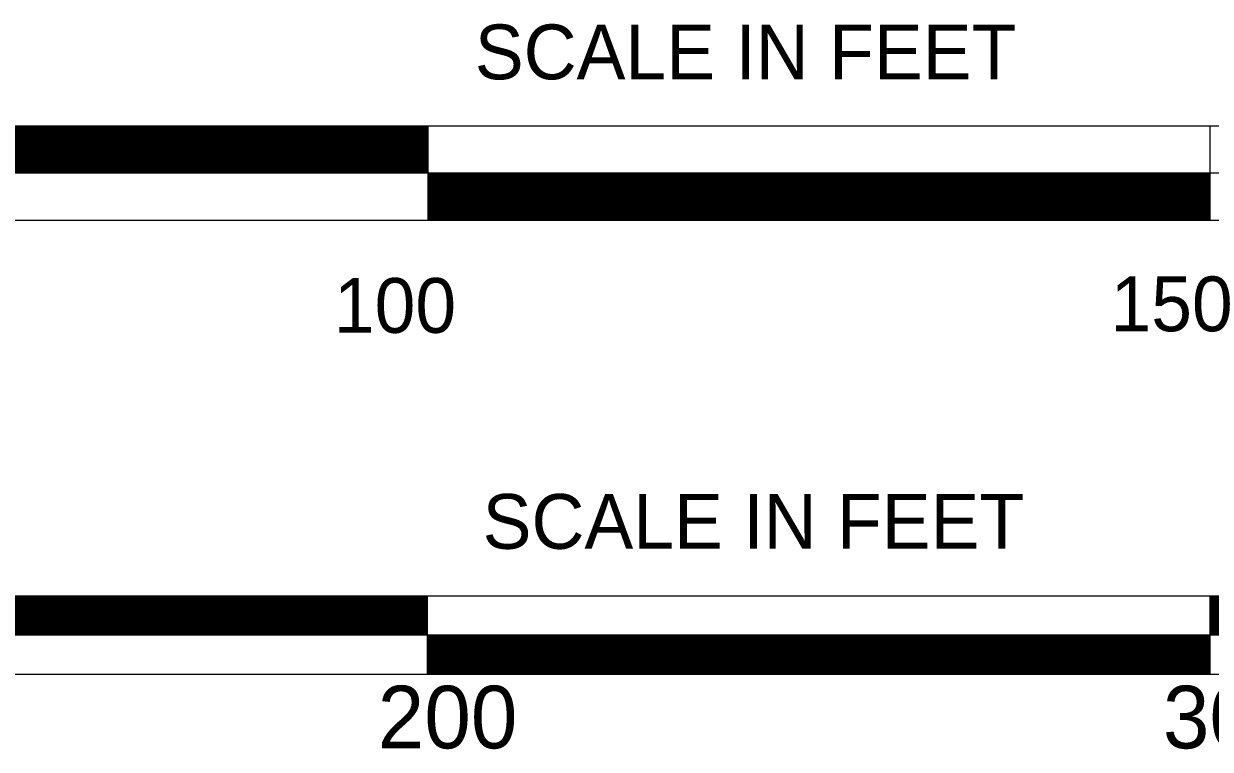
# Model space of a CAD drawing. Extents: x 2147716 to 2176321, y 2125040 to 2131750.
# Drawn here: x 2170114.1 to 2170265.7, y 2129144.4 to 2129237.1 of the extents above; entities that cross this region are included whole.
import ezdxf

# ---------------------------------------------------------------- set-up
doc = ezdxf.new("R2010")
doc.units = 0
doc.layers.add('MAP DATA', color=7, linetype='Continuous')

msp = doc.modelspace()

# ---------------------------------------------------------------- linework, layer by layer
at = {"layer": 'MAP DATA'}
for p, q in [((2170465.63, 2129223.98), (2169965.63, 2129223.98)), ((2170165.73, 2129223.98), (2170065.63, 2129223.98)), ((2170165.73, 2129223.88), (2170065.63, 2129223.88)), ((2170165.73, 2129223.78), (2170065.63, 2129223.78)), ((2170165.73, 2129223.68), (2170065.63, 2129223.68)), ((2170165.73, 2129223.58), (2170065.63, 2129223.58)), ((2170165.73, 2129223.48), (2170065.63, 2129223.48)), ((2170165.73, 2129223.38), (2170065.63, 2129223.38)), ((2170165.73, 2129223.28), (2170065.63, 2129223.28)), ((2170165.73, 2129223.18), (2170065.63, 2129223.18)), ((2170165.73, 2129223.08), (2170065.63, 2129223.08)), ((2170165.73, 2129222.98), (2170065.63, 2129222.98)), ((2170165.73, 2129222.88), (2170065.63, 2129222.88)), ((2170165.73, 2129222.78), (2170065.63, 2129222.78)), ((2170165.73, 2129222.68), (2170065.63, 2129222.68)), ((2170165.73, 2129222.58), (2170065.63, 2129222.58)), ((2170165.73, 2129223.98), (2170165.73, 2129211.98)), ((2170265.63, 2129223.98), (2170265.63, 2129211.98)), ((2170165.73, 2129222.48), (2170065.63, 2129222.48)), ((2170165.73, 2129222.38), (2170065.63, 2129222.38)), ((2170165.73, 2129222.28), (2170065.63, 2129222.28)), ((2170165.73, 2129222.18), (2170065.63, 2129222.18)), ((2170165.73, 2129222.08), (2170065.63, 2129222.08)), ((2170165.73, 2129221.98), (2170065.63, 2129221.98)), ((2170165.73, 2129221.88), (2170065.63, 2129221.88)), ((2170165.73, 2129221.78), (2170065.63, 2129221.78)), ((2170165.73, 2129221.68), (2170065.63, 2129221.68)), ((2170165.73, 2129221.58), (2170065.63, 2129221.58)), ((2170165.73, 2129221.48), (2170065.63, 2129221.48)), ((2170165.73, 2129221.38), (2170065.63, 2129221.38)), ((2170165.73, 2129221.28), (2170065.63, 2129221.28)), ((2170165.73, 2129221.18), (2170065.63, 2129221.18)), ((2170165.73, 2129221.08), (2170065.63, 2129221.08)), ((2170165.73, 2129220.98), (2170065.63, 2129220.98)), ((2170165.73, 2129220.88), (2170065.63, 2129220.88)), ((2170165.73, 2129220.78), (2170065.63, 2129220.78)), ((2170165.73, 2129220.68), (2170065.63, 2129220.68)), ((2170165.73, 2129220.58), (2170065.63, 2129220.58)), ((2170165.73, 2129220.48), (2170065.63, 2129220.48)), ((2170165.73, 2129220.38), (2170065.63, 2129220.38)), ((2170165.73, 2129220.28), (2170065.63, 2129220.28)), ((2170165.73, 2129220.18), (2170065.63, 2129220.18)), ((2170165.73, 2129220.08), (2170065.63, 2129220.08)), ((2170165.73, 2129219.98), (2170065.63, 2129219.98)), ((2170165.73, 2129219.88), (2170065.63, 2129219.88)), ((2170165.73, 2129219.88), (2170065.63, 2129219.88)), ((2170165.73, 2129219.78), (2170065.63, 2129219.78)), ((2170165.73, 2129219.68), (2170065.63, 2129219.68)), ((2170165.73, 2129219.58), (2170065.63, 2129219.58)), ((2170165.73, 2129219.48), (2170065.63, 2129219.48)), ((2170465.63, 2129217.98), (2169965.73, 2129217.98)), ((2170165.73, 2129219.38), (2170065.63, 2129219.38)), ((2170165.73, 2129219.28), (2170065.63, 2129219.28)), ((2170165.73, 2129219.18), (2170065.63, 2129219.18)), ((2170165.73, 2129219.08), (2170065.63, 2129219.08)), ((2170165.73, 2129218.98), (2170065.63, 2129218.98)), ((2170165.73, 2129218.88), (2170065.63, 2129218.88)), ((2170165.73, 2129218.78), (2170065.63, 2129218.78)), ((2170165.73, 2129218.68), (2170065.63, 2129218.68)), ((2170165.73, 2129218.58), (2170065.63, 2129218.58)), ((2170165.73, 2129218.48), (2170065.63, 2129218.48)), ((2170165.73, 2129218.38), (2170065.63, 2129218.38)), ((2170165.73, 2129218.28), (2170065.63, 2129218.28)), ((2170165.73, 2129218.18), (2170065.63, 2129218.18)), ((2170165.73, 2129218.08), (2170065.63, 2129218.08)), ((2170165.73, 2129217.98), (2170065.63, 2129217.98)), ((2170265.63, 2129217.98), (2170165.73, 2129217.98)), ((2170265.63, 2129217.88), (2170165.73, 2129217.88)), ((2170265.63, 2129217.78), (2170165.73, 2129217.78)), ((2170265.63, 2129217.68), (2170165.73, 2129217.68)), ((2170265.63, 2129217.58), (2170165.73, 2129217.58)), ((2170265.63, 2129217.48), (2170165.73, 2129217.48)), ((2170265.63, 2129217.38), (2170165.73, 2129217.38)), ((2170265.63, 2129217.28), (2170165.73, 2129217.28)), ((2170265.63, 2129217.18), (2170165.73, 2129217.18)), ((2170265.63, 2129217.08), (2170165.73, 2129217.08)), ((2170265.63, 2129216.98), (2170165.73, 2129216.98)), ((2170265.63, 2129216.88), (2170165.73, 2129216.88)), ((2170265.63, 2129216.78), (2170165.73, 2129216.78)), ((2170265.63, 2129216.68), (2170165.73, 2129216.68)), ((2170265.63, 2129216.58), (2170165.73, 2129216.58)), ((2170265.63, 2129216.48), (2170165.73, 2129216.48)), ((2170265.63, 2129216.38), (2170165.73, 2129216.38)), ((2170265.63, 2129216.28), (2170165.73, 2129216.28)), ((2170265.63, 2129216.18), (2170165.73, 2129216.18)), ((2170265.63, 2129216.08), (2170165.73, 2129216.08)), ((2170265.63, 2129215.98), (2170165.73, 2129215.98)), ((2170265.63, 2129215.88), (2170165.73, 2129215.88)), ((2170265.63, 2129215.78), (2170165.73, 2129215.78)), ((2170265.63, 2129215.68), (2170165.73, 2129215.68)), ((2170265.63, 2129215.58), (2170165.73, 2129215.58)), ((2170265.63, 2129215.48), (2170165.73, 2129215.48)), ((2170265.63, 2129215.38), (2170165.73, 2129215.38)), ((2170265.63, 2129215.28), (2170165.73, 2129215.28)), ((2170265.63, 2129215.18), (2170165.73, 2129215.18)), ((2170265.63, 2129215.08), (2170165.73, 2129215.08)), ((2170265.63, 2129214.98), (2170165.73, 2129214.98)), ((2170265.63, 2129214.88), (2170165.73, 2129214.88)), ((2170265.63, 2129214.78), (2170165.73, 2129214.78)), ((2170265.63, 2129214.68), (2170165.73, 2129214.68)), ((2170265.63, 2129214.58), (2170165.73, 2129214.58)), ((2170265.63, 2129214.48), (2170165.73, 2129214.48)), ((2170265.63, 2129214.38), (2170165.73, 2129214.38)), ((2170265.63, 2129214.28), (2170165.73, 2129214.28)), ((2170265.63, 2129214.18), (2170165.73, 2129214.18)), ((2170265.63, 2129214.08), (2170165.73, 2129214.08)), ((2170265.63, 2129213.98), (2170165.73, 2129213.98)), ((2170265.63, 2129213.88), (2170165.73, 2129213.88)), ((2170265.63, 2129213.88), (2170165.73, 2129213.88)), ((2170265.63, 2129213.78), (2170165.73, 2129213.78)), ((2170265.63, 2129213.68), (2170165.73, 2129213.68)), ((2170265.63, 2129213.58), (2170165.73, 2129213.58)), ((2170265.63, 2129213.48), (2170165.73, 2129213.48)), ((2169965.63, 2129211.98), (2170465.63, 2129211.98)), ((2170265.63, 2129213.38), (2170165.73, 2129213.38)), ((2170265.63, 2129213.28), (2170165.73, 2129213.28)), ((2170265.63, 2129213.18), (2170165.73, 2129213.18)), ((2170265.63, 2129213.08), (2170165.73, 2129213.08)), ((2170265.63, 2129212.98), (2170165.73, 2129212.98)), ((2170265.63, 2129212.88), (2170165.73, 2129212.88)), ((2170265.63, 2129212.78), (2170165.73, 2129212.78)), ((2170265.63, 2129212.68), (2170165.73, 2129212.68)), ((2170265.63, 2129212.58), (2170165.73, 2129212.58)), ((2170265.63, 2129212.48), (2170165.73, 2129212.48)), ((2170265.63, 2129212.38), (2170165.73, 2129212.38)), ((2170265.63, 2129212.28), (2170165.73, 2129212.28)), ((2170265.63, 2129212.18), (2170165.73, 2129212.18)), ((2170265.63, 2129212.08), (2170165.73, 2129212.08)), ((2169965.63, 2129163.98), (2170465.63, 2129163.98)), ((2170065.63, 2129163.98), (2170165.63, 2129163.98)), ((2170065.63, 2129163.88), (2170165.63, 2129163.88)), ((2170065.63, 2129163.78), (2170165.63, 2129163.78)), ((2170065.63, 2129163.68), (2170165.63, 2129163.68)), ((2170065.63, 2129163.58), (2170165.63, 2129163.58)), ((2170065.63, 2129163.48), (2170165.63, 2129163.48)), ((2170165.63, 2129163.98), (2170165.63, 2129153.98)), ((2170265.63, 2129163.98), (2170265.63, 2129153.98)), ((2170265.63, 2129163.98), (2170365.63, 2129163.98)), ((2170265.63, 2129163.88), (2170365.63, 2129163.88)), ((2170265.63, 2129163.78), (2170365.63, 2129163.78)), ((2170265.63, 2129163.68), (2170365.63, 2129163.68)), ((2170265.63, 2129163.58), (2170365.63, 2129163.58)), ((2170265.63, 2129163.48), (2170365.63, 2129163.48)), ((2170065.63, 2129163.38), (2170165.63, 2129163.38)), ((2170065.63, 2129163.28), (2170165.63, 2129163.28)), ((2170065.63, 2129163.18), (2170165.63, 2129163.18)), ((2170065.63, 2129163.08), (2170165.63, 2129163.08)), ((2170065.63, 2129162.98), (2170165.63, 2129162.98)), ((2170065.63, 2129162.88), (2170165.63, 2129162.88)), ((2170065.63, 2129162.78), (2170165.63, 2129162.78)), ((2170065.63, 2129162.68), (2170165.63, 2129162.68)), ((2170065.63, 2129162.58), (2170165.63, 2129162.58)), ((2170065.63, 2129162.48), (2170165.63, 2129162.48)), ((2170065.63, 2129162.38), (2170165.63, 2129162.38)), ((2170065.63, 2129162.28), (2170165.63, 2129162.28)), ((2170065.63, 2129162.18), (2170165.63, 2129162.18)), ((2170065.63, 2129162.08), (2170165.63, 2129162.08)), ((2170065.63, 2129161.98), (2170165.63, 2129161.98)), ((2170065.63, 2129161.88), (2170165.63, 2129161.88)), ((2170265.63, 2129163.38), (2170365.63, 2129163.38)), ((2170265.63, 2129163.28), (2170365.63, 2129163.28)), ((2170265.63, 2129163.18), (2170365.63, 2129163.18)), ((2170265.63, 2129163.08), (2170365.63, 2129163.08)), ((2170265.63, 2129162.98), (2170365.63, 2129162.98)), ((2170265.63, 2129162.88), (2170365.63, 2129162.88)), ((2170265.63, 2129162.78), (2170365.63, 2129162.78)), ((2170265.63, 2129162.68), (2170365.63, 2129162.68)), ((2170265.63, 2129162.58), (2170365.63, 2129162.58)), ((2170265.63, 2129162.48), (2170365.63, 2129162.48)), ((2170265.63, 2129162.38), (2170365.63, 2129162.38)), ((2170265.63, 2129162.28), (2170365.63, 2129162.28)), ((2170265.63, 2129162.28), (2170365.63, 2129162.28)), ((2170265.63, 2129162.18), (2170365.63, 2129162.18)), ((2170265.63, 2129162.08), (2170365.63, 2129162.08)), ((2170265.63, 2129161.98), (2170365.63, 2129161.98)), ((2170265.63, 2129161.88), (2170365.63, 2129161.88)), ((2170065.63, 2129161.78), (2170165.63, 2129161.78)), ((2170065.63, 2129161.68), (2170165.63, 2129161.68)), ((2170065.63, 2129161.58), (2170165.63, 2129161.58)), ((2170065.63, 2129161.48), (2170165.63, 2129161.48)), ((2170065.63, 2129161.38), (2170165.63, 2129161.38)), ((2170065.63, 2129161.28), (2170165.63, 2129161.28)), ((2170065.63, 2129161.18), (2170165.63, 2129161.18)), ((2170065.63, 2129161.08), (2170165.63, 2129161.08)), ((2170065.63, 2129160.98), (2170165.63, 2129160.98)), ((2170065.63, 2129160.88), (2170165.63, 2129160.88)), ((2170065.63, 2129160.78), (2170165.63, 2129160.78)), ((2170065.63, 2129160.78), (2170165.63, 2129160.78)), ((2170065.63, 2129160.68), (2170165.63, 2129160.68)), ((2170065.63, 2129160.58), (2170165.63, 2129160.58)), ((2170065.63, 2129160.48), (2170165.63, 2129160.48)), ((2170065.63, 2129160.38), (2170165.63, 2129160.38)), ((2170265.63, 2129161.78), (2170365.63, 2129161.78)), ((2170265.63, 2129161.68), (2170365.63, 2129161.68)), ((2170265.63, 2129161.58), (2170365.63, 2129161.58)), ((2170265.63, 2129161.48), (2170365.63, 2129161.48)), ((2170265.63, 2129161.38), (2170365.63, 2129161.38)), ((2170265.63, 2129161.28), (2170365.63, 2129161.28)), ((2170265.63, 2129161.18), (2170365.63, 2129161.18)), ((2170265.63, 2129161.08), (2170365.63, 2129161.08)), ((2170265.63, 2129160.98), (2170365.63, 2129160.98)), ((2170265.63, 2129160.88), (2170365.63, 2129160.88)), ((2170265.63, 2129160.78), (2170365.63, 2129160.78)), ((2170265.63, 2129160.78), (2170365.63, 2129160.78)), ((2170265.63, 2129160.68), (2170365.63, 2129160.68)), ((2170265.63, 2129160.58), (2170365.63, 2129160.58)), ((2170265.63, 2129160.48), (2170365.63, 2129160.48)), ((2170265.63, 2129160.38), (2170365.63, 2129160.38)), ((2169965.63, 2129158.98), (2170465.63, 2129158.98)), ((2170065.63, 2129160.28), (2170165.63, 2129160.28)), ((2170065.63, 2129160.18), (2170165.63, 2129160.18)), ((2170065.63, 2129160.08), (2170165.63, 2129160.08)), ((2170065.63, 2129159.98), (2170165.63, 2129159.98)), ((2170065.63, 2129159.88), (2170165.63, 2129159.88)), ((2170065.63, 2129159.78), (2170165.63, 2129159.78)), ((2170065.63, 2129159.68), (2170165.63, 2129159.68)), ((2170065.63, 2129159.58), (2170165.63, 2129159.58)), ((2170065.63, 2129159.48), (2170165.63, 2129159.48)), ((2170065.63, 2129159.38), (2170165.63, 2129159.38)), ((2170065.63, 2129159.28), (2170165.63, 2129159.28)), ((2170065.63, 2129159.18), (2170165.63, 2129159.18)), ((2170065.63, 2129159.08), (2170165.63, 2129159.08)), ((2170065.63, 2129158.98), (2170165.63, 2129158.98)), ((2170265.63, 2129158.88), (2170165.63, 2129158.88)), ((2170265.63, 2129160.28), (2170365.63, 2129160.28)), ((2170265.63, 2129160.18), (2170365.63, 2129160.18)), ((2170265.63, 2129160.08), (2170365.63, 2129160.08)), ((2170265.63, 2129159.98), (2170365.63, 2129159.98)), ((2170265.63, 2129159.88), (2170365.63, 2129159.88)), ((2170265.63, 2129159.78), (2170365.63, 2129159.78)), ((2170265.63, 2129159.68), (2170365.63, 2129159.68)), ((2170265.63, 2129159.58), (2170365.63, 2129159.58)), ((2170265.63, 2129159.48), (2170365.63, 2129159.48)), ((2170265.63, 2129159.38), (2170365.63, 2129159.38)), ((2170265.63, 2129159.28), (2170365.63, 2129159.28)), ((2170265.63, 2129159.18), (2170365.63, 2129159.18)), ((2170265.63, 2129159.08), (2170365.63, 2129159.08)), ((2170265.63, 2129158.98), (2170365.63, 2129158.98)), ((2170265.63, 2129158.78), (2170165.63, 2129158.78)), ((2170265.63, 2129158.68), (2170165.63, 2129158.68)), ((2170265.63, 2129158.58), (2170165.63, 2129158.58)), ((2170265.63, 2129158.48), (2170165.63, 2129158.48)), ((2170265.63, 2129158.38), (2170165.63, 2129158.38)), ((2170265.63, 2129158.28), (2170165.63, 2129158.28)), ((2170265.63, 2129158.18), (2170165.63, 2129158.18)), ((2170265.63, 2129158.08), (2170165.63, 2129158.08)), ((2170265.63, 2129157.98), (2170165.63, 2129157.98)), ((2170265.63, 2129157.88), (2170165.63, 2129157.88)), ((2170265.63, 2129157.78), (2170165.63, 2129157.78)), ((2170265.63, 2129157.68), (2170165.63, 2129157.68)), ((2170265.63, 2129157.58), (2170165.63, 2129157.58)), ((2170265.63, 2129157.48), (2170165.63, 2129157.48)), ((2170265.63, 2129157.38), (2170165.63, 2129157.38)), ((2170265.63, 2129157.28), (2170165.63, 2129157.28)), ((2170265.63, 2129157.18), (2170165.63, 2129157.18)), ((2170265.63, 2129157.08), (2170165.63, 2129157.08)), ((2170265.63, 2129156.98), (2170165.63, 2129156.98)), ((2170265.63, 2129156.88), (2170165.63, 2129156.88)), ((2170265.63, 2129156.78), (2170165.63, 2129156.78)), ((2170265.63, 2129156.68), (2170165.63, 2129156.68)), ((2170265.63, 2129156.58), (2170165.63, 2129156.58)), ((2170265.63, 2129156.48), (2170165.63, 2129156.48)), ((2170265.63, 2129156.38), (2170165.63, 2129156.38)), ((2170265.63, 2129156.28), (2170165.63, 2129156.28)), ((2170265.63, 2129156.18), (2170165.63, 2129156.18)), ((2170265.63, 2129156.08), (2170165.63, 2129156.08)), ((2170265.63, 2129155.98), (2170165.63, 2129155.98)), ((2170265.63, 2129155.88), (2170165.63, 2129155.88)), ((2170265.63, 2129155.78), (2170165.63, 2129155.78)), ((2170265.63, 2129155.68), (2170165.63, 2129155.68)), ((2170265.63, 2129155.58), (2170165.63, 2129155.58)), ((2170265.63, 2129155.58), (2170165.63, 2129155.58)), ((2170265.63, 2129155.48), (2170165.63, 2129155.48)), ((2170265.63, 2129155.38), (2170165.63, 2129155.38)), ((2170265.63, 2129155.28), (2170165.63, 2129155.28)), ((2170265.63, 2129155.18), (2170165.63, 2129155.18)), ((2170265.63, 2129155.08), (2170165.63, 2129155.08)), ((2170265.63, 2129154.98), (2170165.63, 2129154.98)), ((2170265.63, 2129154.88), (2170165.63, 2129154.88)), ((2170265.63, 2129154.78), (2170165.63, 2129154.78)), ((2170265.63, 2129154.68), (2170165.63, 2129154.68)), ((2170265.63, 2129154.58), (2170165.63, 2129154.58)), ((2170265.63, 2129154.48), (2170165.63, 2129154.48)), ((2170265.63, 2129154.38), (2170165.63, 2129154.38)), ((2169965.63, 2129153.98), (2170465.63, 2129153.98)), ((2170265.63, 2129154.28), (2170165.63, 2129154.28)), ((2170265.63, 2129154.18), (2170165.63, 2129154.18)), ((2170265.63, 2129154.08), (2170165.63, 2129154.08)), ((2170265.63, 2129153.98), (2170165.63, 2129153.98))]:
    msp.add_line(p, q, dxfattribs=at)

# ---------------------------------------------------------------- texts
for s, height, p in [('SCALE IN FEET', 7.0002, (2170171.73, 2129229.98)), ('100', 7, (2170153.73, 2129197.58)), ('150', 7, (2170252.93, 2129197.78)), ('SCALE IN FEET', 7.0002, (2170172.73, 2129169.98)), ('200', 8, (2170159.33, 2129144.48)), ('300', 8, (2170259.63, 2129144.48))]:
    msp.add_text(s, height=height, dxfattribs=at).set_placement(p)

doc.saveas('drawing.dxf')
